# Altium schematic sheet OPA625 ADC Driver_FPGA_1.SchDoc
size 431 x 279 mm; Date: Not shown in title block; ApprovedBy: Not shown in title block; CheckedBy: Not shown in title block; Author: Not shown in title block; CompanyName: Not shown in title block; Engineer: Not shown in title block; Organization: Not shown in title block; Address1: Not shown in title block; Address2: Not shown in title block; Address3: Not shown in title block; Address4: Not shown in title block; DocumentNumber: 6; Revision: Use project parameter SCH_Rev; SheetNumber: 6; SheetTotal: 8; PageSetup: Record=PageOptions¦CenterHorizontal=True¦CenterVertical=True¦PrintScale=1.00¦XCorrection=1.00¦YCorrection=1.00¦PrintKind=0¦BorderSize=5000000¦LeftOffset=0¦BottomOffset=0¦Orientation=2¦PaperLength=1000¦PaperWidth=1000¦Scale=100¦PaperSource=15¦PrintQuality=600¦MediaType=1¦DitherType=10¦PaperKind=Letter¦PrintScaleMode=1
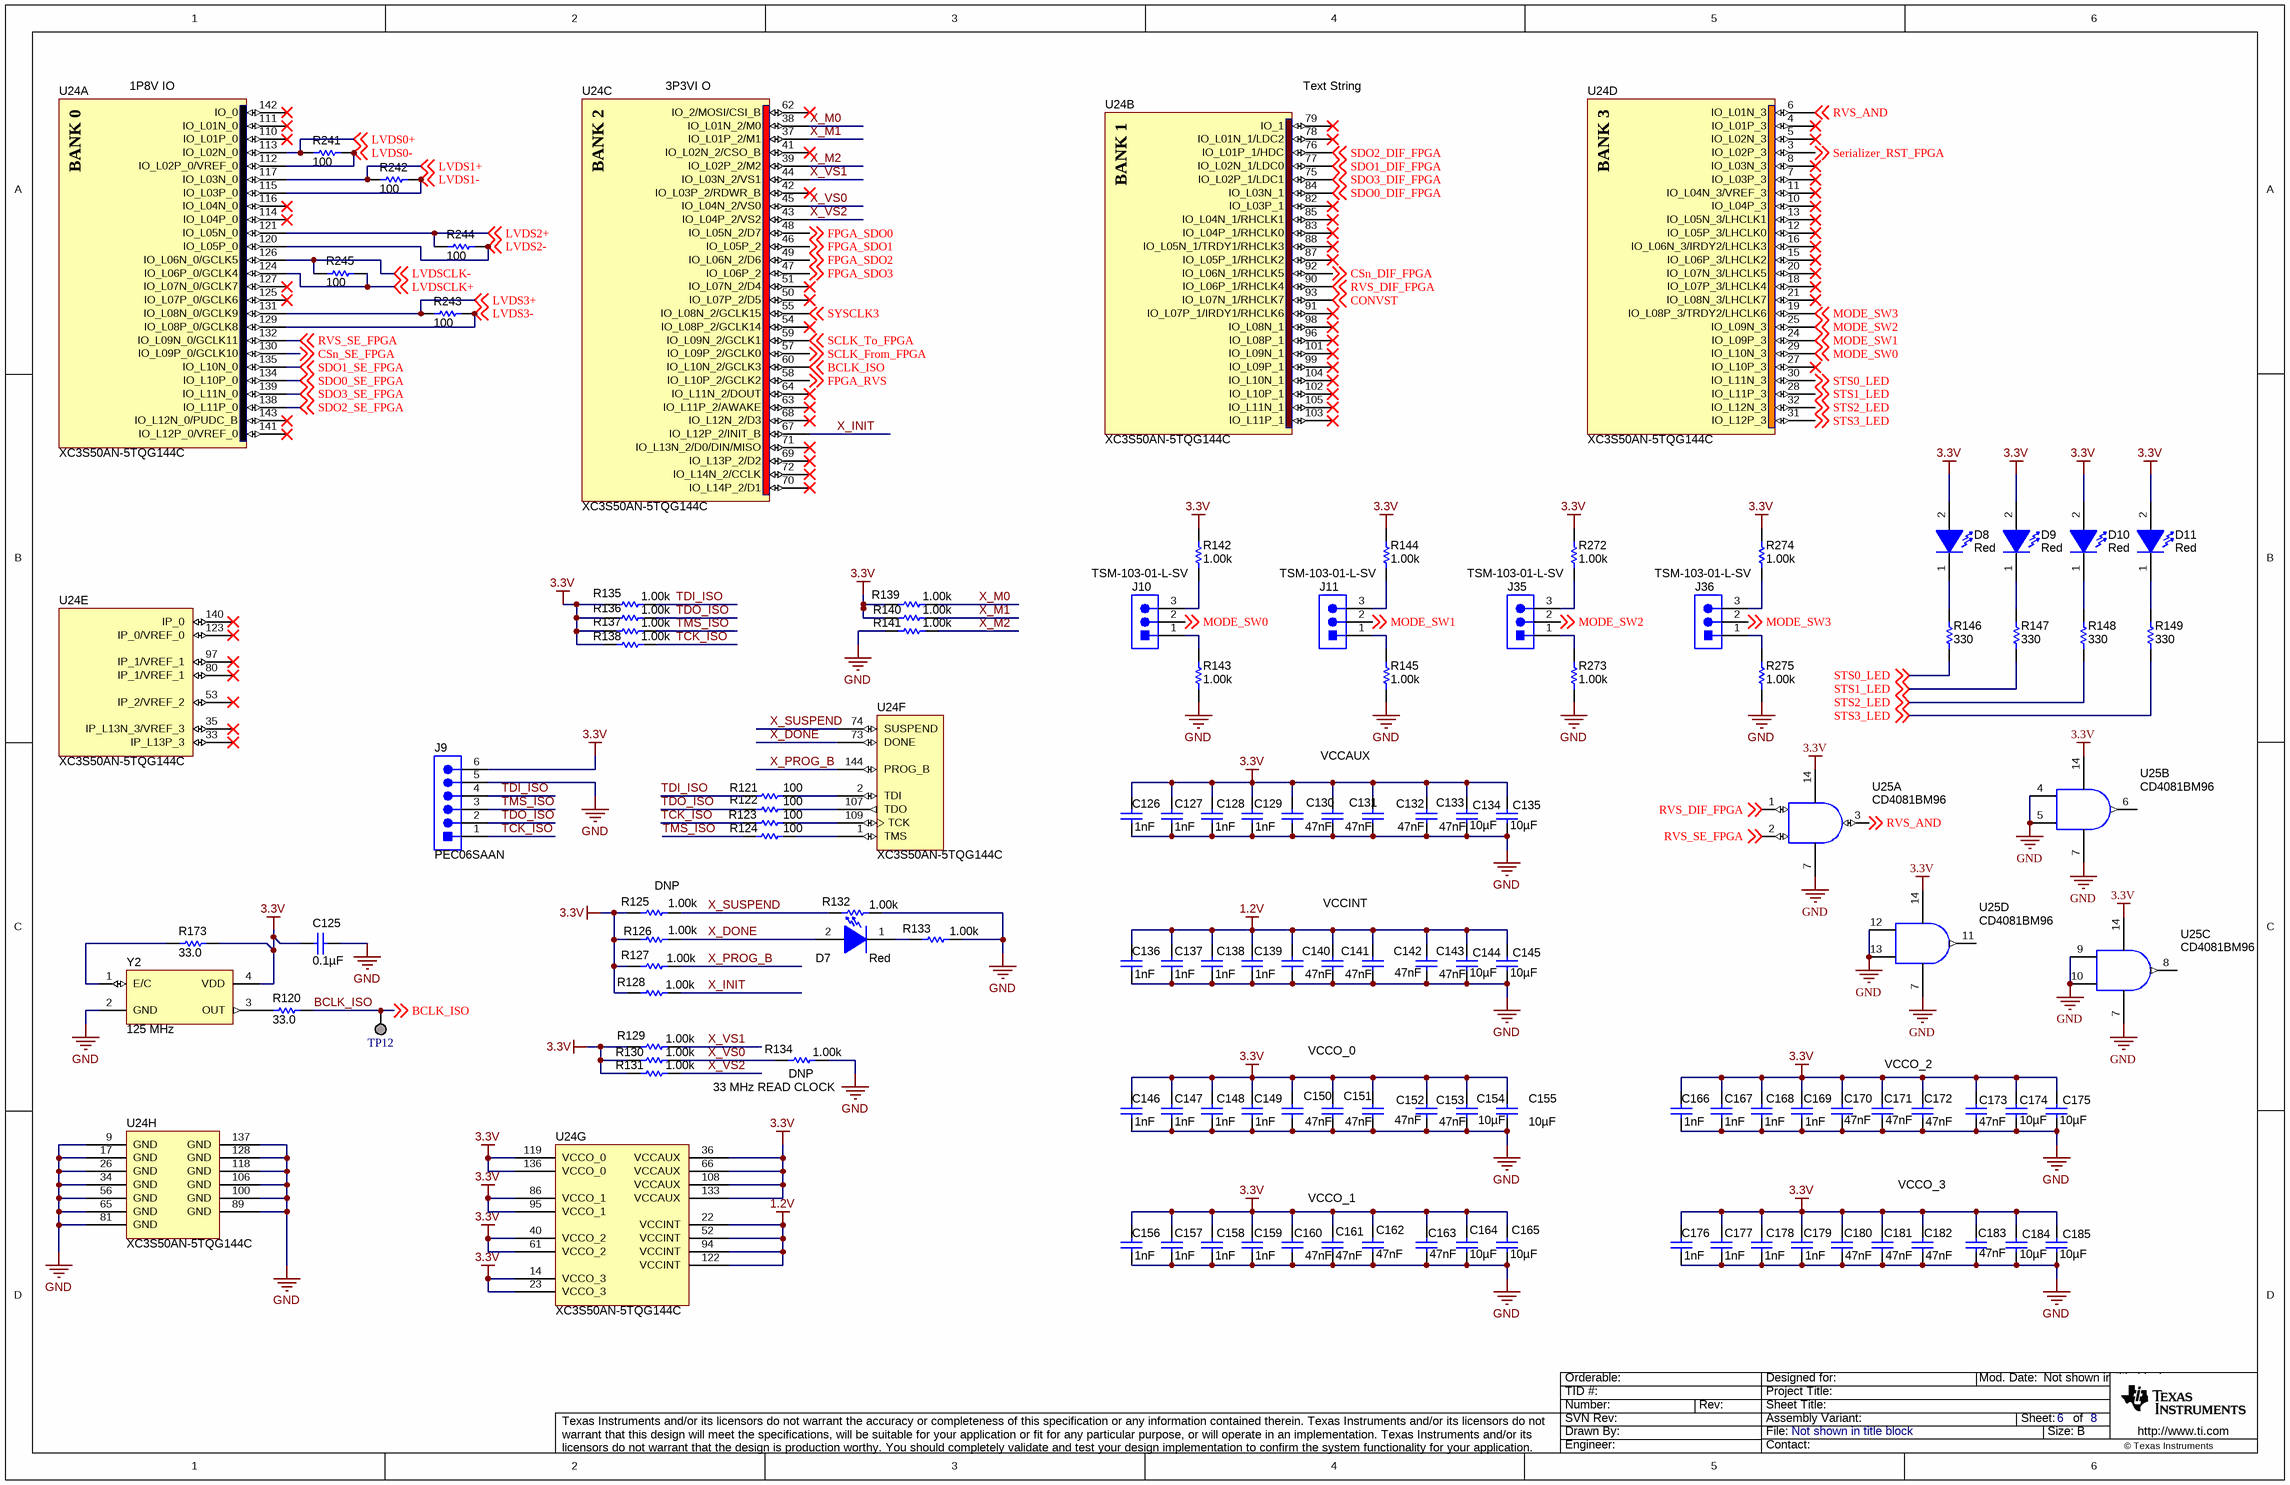
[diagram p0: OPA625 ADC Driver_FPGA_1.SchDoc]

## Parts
C125  ValueDisplayed: 0.1µF  [0402]  (hidden comment: GRM155R71C104KA88D)
C126  ValueDisplayed: 1nF  [0402]  (hidden comment: C1005X7R1H102M)
C127  ValueDisplayed: 1nF  [0402]  (hidden comment: C1005X7R1H102M)
C128  ValueDisplayed: 1nF  [0402]  (hidden comment: C1005X7R1H102M)
C129  ValueDisplayed: 1nF  [0402]  (hidden comment: C1005X7R1H102M)
C130  ValueDisplayed: 47nF  [0402]  (hidden comment: GRM155R61A473KA01D)
C131  ValueDisplayed: 47nF  [0402]  (hidden comment: GRM155R61A473KA01D)
C132  ValueDisplayed: 47nF  [0402]  (hidden comment: GRM155R61A473KA01D)
C133  ValueDisplayed: 47nF  [0402]  (hidden comment: GRM155R61A473KA01D)
C134  ValueDisplayed: 10µF  [0603_120]  (hidden comment: ZRB18AD71A106KE01L)
C135  ValueDisplayed: 10µF  [0603_120]  (hidden comment: ZRB18AD71A106KE01L)
C136  ValueDisplayed: 1nF  [0402]  (hidden comment: C1005X7R1H102M)
C137  ValueDisplayed: 1nF  [0402]  (hidden comment: C1005X7R1H102M)
C138  ValueDisplayed: 1nF  [0402]  (hidden comment: C1005X7R1H102M)
C139  ValueDisplayed: 1nF  [0402]  (hidden comment: C1005X7R1H102M)
C140  ValueDisplayed: 47nF  [0402]  (hidden comment: GRM155R61A473KA01D)
C141  ValueDisplayed: 47nF  [0402]  (hidden comment: GRM155R61A473KA01D)
C142  ValueDisplayed: 47nF  [0402]  (hidden comment: GRM155R61A473KA01D)
C143  ValueDisplayed: 47nF  [0402]  (hidden comment: GRM155R61A473KA01D)
C144  ValueDisplayed: 10µF  [0603_120]  (hidden comment: ZRB18AD71A106KE01L)
C145  ValueDisplayed: 10µF  [0603_120]  (hidden comment: ZRB18AD71A106KE01L)
C146  ValueDisplayed: 1nF  [0402]  (hidden comment: C1005X7R1H102M)
C147  ValueDisplayed: 1nF  [0402]  (hidden comment: C1005X7R1H102M)
C148  ValueDisplayed: 1nF  [0402]  (hidden comment: C1005X7R1H102M)
C149  ValueDisplayed: 1nF  [0402]  (hidden comment: C1005X7R1H102M)
C150  ValueDisplayed: 47nF  [0402]  (hidden comment: GRM155R61A473KA01D)
C151  ValueDisplayed: 47nF  [0402]  (hidden comment: GRM155R61A473KA01D)
C152  ValueDisplayed: 47nF  [0402]  (hidden comment: GRM155R61A473KA01D)
C153  ValueDisplayed: 47nF  [0402]  (hidden comment: GRM155R61A473KA01D)
C154  ValueDisplayed: 10µF  [0603_120]  (hidden comment: ZRB18AD71A106KE01L)
C155  ValueDisplayed: 10µF  [0603_120]  (hidden comment: ZRB18AD71A106KE01L)
C156  ValueDisplayed: 1nF  [0402]  (hidden comment: C1005X7R1H102M)
C157  ValueDisplayed: 1nF  [0402]  (hidden comment: C1005X7R1H102M)
C158  ValueDisplayed: 1nF  [0402]  (hidden comment: C1005X7R1H102M)
C159  ValueDisplayed: 1nF  [0402]  (hidden comment: C1005X7R1H102M)
C160  ValueDisplayed: 47nF  [0402]  (hidden comment: GRM155R61A473KA01D)
C161  ValueDisplayed: 47nF  [0402]  (hidden comment: GRM155R61A473KA01D)
C162  ValueDisplayed: 47nF  [0402]  (hidden comment: GRM155R61A473KA01D)
C163  ValueDisplayed: 47nF  [0402]  (hidden comment: GRM155R61A473KA01D)
C164  ValueDisplayed: 10µF  [0603_120]  (hidden comment: ZRB18AD71A106KE01L)
C165  ValueDisplayed: 10µF  [0603_120]  (hidden comment: ZRB18AD71A106KE01L)
C166  ValueDisplayed: 1nF  [0402]  (hidden comment: C1005X7R1H102M)
C167  ValueDisplayed: 1nF  [0402]  (hidden comment: C1005X7R1H102M)
C168  ValueDisplayed: 1nF  [0402]  (hidden comment: C1005X7R1H102M)
C169  ValueDisplayed: 1nF  [0402]  (hidden comment: C1005X7R1H102M)
C170  ValueDisplayed: 47nF  [0402]  (hidden comment: GRM155R61A473KA01D)
C171  ValueDisplayed: 47nF  [0402]  (hidden comment: GRM155R61A473KA01D)
C172  ValueDisplayed: 47nF  [0402]  (hidden comment: GRM155R61A473KA01D)
C173  ValueDisplayed: 47nF  [0402]  (hidden comment: GRM155R61A473KA01D)
C174  ValueDisplayed: 10µF  [0603_120]  (hidden comment: ZRB18AD71A106KE01L)
C175  ValueDisplayed: 10µF  [0603_120]  (hidden comment: ZRB18AD71A106KE01L)
C176  ValueDisplayed: 1nF  [0402]  (hidden comment: C1005X7R1H102M)
C177  ValueDisplayed: 1nF  [0402]  (hidden comment: C1005X7R1H102M)
C178  ValueDisplayed: 1nF  [0402]  (hidden comment: C1005X7R1H102M)
C179  ValueDisplayed: 1nF  [0402]  (hidden comment: C1005X7R1H102M)
C180  ValueDisplayed: 47nF  [0402]  (hidden comment: GRM155R61A473KA01D)
C181  ValueDisplayed: 47nF  [0402]  (hidden comment: GRM155R61A473KA01D)
C182  ValueDisplayed: 47nF  [0402]  (hidden comment: GRM155R61A473KA01D)
C183  ValueDisplayed: 47nF  [0402]  (hidden comment: GRM155R61A473KA01D)
C184  ValueDisplayed: 10µF  [0603_120]  (hidden comment: ZRB18AD71A106KE01L)
C185  ValueDisplayed: 10µF  [0603_120]  (hidden comment: ZRB18AD71A106KE01L)
D7  value Red  [WL-SMCW_RED]  (hidden comment: 150060RS75000)
D8  value Red  [WL-SMCW_RED]  (hidden comment: 150060RS75000)
D9  value Red  [WL-SMCW_RED]  (hidden comment: 150060RS75000)
D10  value Red  [WL-SMCW_RED]  (hidden comment: 150060RS75000)
D11  value Red  [WL-SMCW_RED]  (hidden comment: 150060RS75000)
J9  PEC06SAAN  [Sullins_PEC06SAAN]
J10  TSM-103-01-L-SV  [Samtec_TSM-103-01-X-SV]
J11  TSM-103-01-L-SV  [Samtec_TSM-103-01-X-SV]
J35  TSM-103-01-L-SV  [Samtec_TSM-103-01-X-SV]
J36  TSM-103-01-L-SV  [Samtec_TSM-103-01-X-SV]
R120  ValueDisplayed: 33.0  [0603]  (hidden comment: RC0603FR-0733RL)
R121  ValueDisplayed: 100  [0603]  (hidden comment: RG1608P-101-B-T5)
R122  ValueDisplayed: 100  [0603]  (hidden comment: RG1608P-101-B-T5)
R123  ValueDisplayed: 100  [0603]  (hidden comment: RG1608P-101-B-T5)
R124  ValueDisplayed: 100  [0603]  (hidden comment: RG1608P-101-B-T5)
R125  ValueDisplayed: 1.00k  [0603]  (hidden comment: RC0603FR-071KL)
R126  ValueDisplayed: 1.00k  [0603]  (hidden comment: RC0603FR-071KL)
R127  ValueDisplayed: 1.00k  [0603]  (hidden comment: RC0603FR-071KL)
R128  ValueDisplayed: 1.00k  [0603]  (hidden comment: RC0603FR-071KL)
R129  ValueDisplayed: 1.00k  [0603]  (hidden comment: RC0603FR-071KL)
R130  ValueDisplayed: 1.00k  [0603]  (hidden comment: RC0603FR-071KL)
R131  ValueDisplayed: 1.00k  [0603]  (hidden comment: RC0603FR-071KL)
R132  ValueDisplayed: 1.00k  [0603]  (hidden comment: RC0603FR-071KL)
R133  ValueDisplayed: 1.00k  [0603]  (hidden comment: RC0603FR-071KL)
R134  ValueDisplayed: 1.00k  [0603]  (hidden comment: RC0603FR-071KL)
R135  ValueDisplayed: 1.00k  [0603]  (hidden comment: RC0603FR-071KL)
R136  ValueDisplayed: 1.00k  [0603]  (hidden comment: RC0603FR-071KL)
R137  ValueDisplayed: 1.00k  [0603]  (hidden comment: RC0603FR-071KL)
R138  ValueDisplayed: 1.00k  [0603]  (hidden comment: RC0603FR-071KL)
R139  ValueDisplayed: 1.00k  [0603]  (hidden comment: RC0603FR-071KL)
R140  ValueDisplayed: 1.00k  [0603]  (hidden comment: RC0603FR-071KL)
R141  ValueDisplayed: 1.00k  [0603]  (hidden comment: RC0603FR-071KL)
R142  ValueDisplayed: 1.00k  [0603]  (hidden comment: RC0603FR-071KL)
R143  ValueDisplayed: 1.00k  [0603]  (hidden comment: RC0603FR-071KL)
R144  ValueDisplayed: 1.00k  [0603]  (hidden comment: RC0603FR-071KL)
R145  ValueDisplayed: 1.00k  [0603]  (hidden comment: RC0603FR-071KL)
R146  ValueDisplayed: 330  [0603]  (hidden comment: RC0603JR-07330RL)
R147  ValueDisplayed: 330  [0603]  (hidden comment: RC0603JR-07330RL)
R148  ValueDisplayed: 330  [0603]  (hidden comment: RC0603JR-07330RL)
R149  ValueDisplayed: 330  [0603]  (hidden comment: RC0603JR-07330RL)
R173  ValueDisplayed: 33.0  [0603]  (hidden comment: RC0603FR-0733RL)
R241  ValueDisplayed: 100  [0402L]  (hidden comment: MCS0402MD1000BE100)
R242  ValueDisplayed: 100  [0402L]  (hidden comment: MCS0402MD1000BE100)
R243  ValueDisplayed: 100  [0402L]  (hidden comment: MCS0402MD1000BE100)
R244  ValueDisplayed: 100  [0402L]  (hidden comment: MCS0402MD1000BE100)
R245  ValueDisplayed: 100  [0402L]  (hidden comment: MCS0402MD1000BE100)
R272  ValueDisplayed: 1.00k  [0603]  (hidden comment: RC0603FR-071KL)
R273  ValueDisplayed: 1.00k  [0603]  (hidden comment: RC0603FR-071KL)
R274  ValueDisplayed: 1.00k  [0603]  (hidden comment: RC0603FR-071KL)
R275  ValueDisplayed: 1.00k  [0603]  (hidden comment: RC0603FR-071KL)
TP12  Pogo Pad  [PogoPad]  (value not drawn)  (no BOM)
U24  XC3S50AN-5TQG144C  [TQ144_N]  (parts A,B,C,D,E,F,G,H of 8)
U25  CD4081BM96  [D0014A_N]  (parts A,B,C,D of 4)
Y2  Frequency: 125 MHz  [Vectron_VCC1]  (hidden comment: VCC1-B3B-125M000000)

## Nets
1.2V: C136.1 C137.1 C138.1 C139.1 C140.1 C141.1 C142.1 C143.1 C144.1 C145.1 U24.22(VCCINT) U24.52(VCCINT) U24.94(VCCINT) U24.122(VCCINT)
3.3V: C125.1 C126.1 C127.1 C128.1 C129.1 C130.1 C131.1 C132.1 C133.1 C134.1 C135.1 C146.1 C147.1 C148.1 C149.1 C150.1 C151.1 C152.1 C153.1 C154.1 C155.1 C156.1 C157.1 C158.1 C159.1 C160.1 C161.1 C162.1 C163.1 C164.1 C165.1 C166.1 C167.1 C168.1 C169.1 C170.1 C171.1 C172.1 C173.1 C174.1 C175.1 C176.1 C177.1 C178.1 C179.1 C180.1 C181.1 C182.1 C183.1 C184.1 C185.1 D8.2(A) D9.2(A) D10.2(A) D11.2(A) J9.6 R125.2 R126.1 R127.1 R128.1 R129.1 R130.1 R131.1 R135.1 R136.1 R137.1 R138.1 R139.1 R140.1 R142.2 R144.2 R173.2 R272.2 R274.2 U24.14(VCCO_3) U24.23(VCCO_3) U24.36(VCCAUX) U24.40(VCCO_2) U24.61(VCCO_2) U24.66(VCCAUX) U24.86(VCCO_1) U24.95(VCCO_1) U24.108(VCCAUX) U24.119(VCCO_0) U24.133(VCCAUX) U24.136(VCCO_0) U25.14(VCC) Y2.4(VDD)
GND: C125.2 C126.2 C127.2 C128.2 C129.2 C130.2 C131.2 C132.2 C133.2 C134.2 C135.2 C136.2 C137.2 C138.2 C139.2 C140.2 C141.2 C142.2 C143.2 C144.2 C145.2 C146.2 C147.2 C148.2 C149.2 C150.2 C151.2 C152.2 C153.2 C154.2 C155.2 C156.2 C157.2 C158.2 C159.2 C160.2 C161.2 C162.2 C163.2 C164.2 C165.2 C166.2 C167.2 C168.2 C169.2 C170.2 C171.2 C172.2 C173.2 C174.2 C175.2 C176.2 C177.2 C178.2 C179.2 C180.2 C181.2 C182.2 C183.2 C184.2 C185.2 J9.5 R132.1 R133.1 R134.2 R141.1 R143.1 R145.1 R273.1 R275.1 U24.9(GND) U24.17(GND) U24.26(GND) U24.34(GND) U24.56(GND) U24.65(GND) U24.81(GND) U24.89(GND) U24.100(GND) U24.106(GND) U24.118(GND) U24.128(GND) U24.137(GND) U25.4(2A) U25.5(2B) U25.7(GND) U25.9(3A) U25.10(3B) U25.12(4A) U25.13(4B) Y2.2(GND)
BCLK_ISO: R120.2 TP12.1 U24.60(IO_L10N_2/GCLK3) ; off-sheet BCLK_ISO
CONVST: U24.93(IO_L07N_1/RHCLK7) ; off-sheet CONVST
CSn_DIF_FPGA: U24.92(IO_L06N_1/RHCLK5) ; off-sheet CSn_DIF_FPGA
CSn_SE_FPGA: U24.130(IO_L09P_0/GCLK10) ; off-sheet CSn_SE_FPGA
FPGA_RVS: U24.58(IO_L10P_2/GCLK2) ; off-sheet FPGA_RVS
FPGA_SDO0: U24.48(IO_L05N_2/D7) ; off-sheet FPGA_SDO0
FPGA_SDO1: U24.46(IO_L05P_2) ; off-sheet FPGA_SDO1
FPGA_SDO2: U24.49(IO_L06N_2/D6) ; off-sheet FPGA_SDO2
FPGA_SDO3: U24.47(IO_L06P_2) ; off-sheet FPGA_SDO3
LVDS0+: R241.1 U24.113(IO_L02N_0) ; off-sheet LVDS0+
LVDS0-: R241.2 U24.112(IO_L02P_0/VREF_0) ; off-sheet LVDS0-
LVDS1+: R242.1 U24.117(IO_L03N_0) ; off-sheet LVDS1+
LVDS1-: R242.2 U24.115(IO_L03P_0) ; off-sheet LVDS1-
LVDS2+: R244.1 U24.121(IO_L05N_0) ; off-sheet LVDS2+
LVDS2-: R244.2 U24.120(IO_L05P_0) ; off-sheet LVDS2-
LVDS3+: R243.1 U24.131(IO_L08N_0/GCLK9) ; off-sheet LVDS3+
LVDS3-: R243.2 U24.129(IO_L08P_0/GCLK8) ; off-sheet LVDS3-
LVDSCLK+: R245.2 U24.124(IO_L06P_0/GCLK4) ; off-sheet LVDSCLK+
LVDSCLK-: R245.1 U24.126(IO_L06N_0/GCLK5) ; off-sheet LVDSCLK-
MODE_SW0: J10.2 U24.29(IO_L10N_3) ; off-sheet MODE_SW0
MODE_SW1: J11.2 U24.24(IO_L09P_3) ; off-sheet MODE_SW1
MODE_SW2: J35.2 U24.25(IO_L09N_3) ; off-sheet MODE_SW2
MODE_SW3: J36.2 U24.19(IO_L08P_3/TRDY2/LHCLK6) ; off-sheet MODE_SW3
RVS_AND: U24.6(IO_L01N_3) U25.3(1Y) ; off-sheet RVS_AND
RVS_DIF_FPGA: U24.90(IO_L06P_1/RHCLK4) U25.1(1A) ; off-sheet RVS_DIF_FPGA
RVS_SE_FPGA: U24.132(IO_L09N_0/GCLK11) U25.2(1B) ; off-sheet RVS_SE_FPGA
SCLK_From_FPGA: U24.57(IO_L09P_2/GCLK0) ; off-sheet SCLK_From_FPGA
SCLK_To_FPGA: U24.59(IO_L09N_2/GCLK1) ; off-sheet SCLK_To_FPGA
SDO0_DIF_FPGA: U24.84(IO_L03N_1) ; off-sheet SDO0_DIF_FPGA
SDO0_SE_FPGA: U24.134(IO_L10P_0) ; off-sheet SDO0_SE_FPGA
SDO1_DIF_FPGA: U24.77(IO_L02N_1/LDC0) ; off-sheet SDO1_DIF_FPGA
SDO1_SE_FPGA: U24.135(IO_L10N_0) ; off-sheet SDO1_SE_FPGA
SDO2_DIF_FPGA: U24.76(IO_L01P_1/HDC) ; off-sheet SDO2_DIF_FPGA
SDO2_SE_FPGA: U24.138(IO_L11P_0) ; off-sheet SDO2_SE_FPGA
SDO3_DIF_FPGA: U24.75(IO_L02P_1/LDC1) ; off-sheet SDO3_DIF_FPGA
SDO3_SE_FPGA: U24.139(IO_L11N_0) ; off-sheet SDO3_SE_FPGA
Serializer_RST_FPGA: U24.3(IO_L02P_3) ; off-sheet Serializer_RST_FPGA
STS0_LED: R146.1 U24.30(IO_L11N_3) ; off-sheet STS0_LED
STS1_LED: R147.1 U24.28(IO_L11P_3) ; off-sheet STS1_LED
STS2_LED: R148.1 U24.32(IO_L12N_3) ; off-sheet STS2_LED
STS3_LED: R149.1 U24.31(IO_L12P_3) ; off-sheet STS3_LED
SYSCLK3: U24.55(IO_L08N_2/GCLK15) ; off-sheet SYSCLK3
TCK_ISO: J9.1 R123.1 R138.2
TDI_ISO: J9.4 R121.1 R135.2
TDO_ISO: J9.2 R122.1 R136.2
TMS_ISO: J9.3 R124.1 R137.2
X_DONE: D7.2(A) R126.2 U24.73(DONE)
X_INIT: R128.2 U24.67(IO_L12P_2/INIT_B)
X_M0: R139.2 U24.38(IO_L01N_2/M0)
X_M1: R140.2 U24.37(IO_L01P_2/M1)
X_M2: R141.2 U24.39(IO_L02P_2/M2)
X_PROG_B: R127.2 U24.144(PROG_B)
X_SUSPEND: R125.1 R132.2 U24.74(SUSPEND)
X_VS0: R130.2 R134.1 U24.45(IO_L04N_2/VS0)
X_VS1: R129.2 U24.44(IO_L03N_2/VS1)
X_VS2: R131.2 U24.43(IO_L04P_2/VS2)
NetD7_1: D7.1(K) R133.2
NetD8_1: D8.1(K) R146.2
NetD9_1: D9.1(K) R147.2
NetD10_1: D10.1(K) R148.2
NetD11_1: D11.1(K) R149.2
NetJ10_1: J10.1 R143.2
NetJ10_3: J10.3 R142.1
NetJ11_1: J11.1 R145.2
NetJ11_3: J11.3 R144.1
NetJ35_1: J35.1 R273.2
NetJ35_3: J35.3 R272.1
NetJ36_1: J36.1 R275.2
NetJ36_3: J36.3 R274.1
NetR120_1: R120.1 Y2.3(OUT)
NetR121_2: R121.2 U24.2(TDI)
NetR122_2: R122.2 U24.107(TDO)
NetR123_2: R123.2 U24.109(TCK)
NetR124_2: R124.2 U24.1(TMS)
NetR173_1: R173.1 Y2.1(E/C)

Not connected (* = marked no-connect by the designer): U24 4(IO_L01P_3)* 5(IO_L02N_3)* 7(IO_L03P_3)* 8(IO_L03N_3)* 10(IO_L04P_3)* 11(IO_L04N_3/VREF_3)* 12(IO_L05P_3/LHCLK0)* 13(IO_L05N_3/LHCLK1)* 15(IO_L06P_3/LHCLK2)* 16(IO_L06N_3/IRDY2/LHCLK3)* 18(IO_L07P_3/LHCLK4)* 20(IO_L07N_3/LHCLK5)* 21(IO_L08N_3/LHCLK7)* 27(IO_L10P_3)* 33(IP_L13P_3)* 35(IP_L13N_3/VREF_3)* 41(IO_L02N_2/CSO_B)* 42(IO_L03P_2/RDWR_B)* 50(IO_L07P_2/D5)* 51(IO_L07N_2/D4)* 53(IP_2/VREF_2)* 54(IO_L08P_2/GCLK14)* 62(IO_2/MOSI/CSI_B)* 63(IO_L11P_2/AWAKE)* 64(IO_L11N_2/DOUT)* 68(IO_L12N_2/D3)* 69(IO_L13P_2/D2)* 70(IO_L14P_2/D1)* 71(IO_L13N_2/D0/DIN/MISO)* 72(IO_L14N_2/CCLK)* 78(IO_L01N_1/LDC2)* 79(IO_1)* 80(IP_1/VREF_1)* 82(IO_L03P_1)* 83(IO_L04P_1/RHCLK0)* 85(IO_L04N_1/RHCLK1)* 87(IO_L05P_1/RHCLK2)* 88(IO_L05N_1/TRDY1/RHCLK3)* 91(IO_L07P_1/IRDY1/RHCLK6)* 96(IO_L08P_1)* 97(IP_1/VREF_1)* 98(IO_L08N_1)* 99(IO_L09P_1)* 101(IO_L09N_1)* 102(IO_L10P_1)* 103(IO_L11P_1)* 104(IO_L10N_1)* 105(IO_L11N_1)* 110(IO_L01P_0)* 111(IO_L01N_0)* 114(IO_L04P_0)* 116(IO_L04N_0)* 123(IP_0/VREF_0)* 125(IO_L07P_0/GCLK6)* 127(IO_L07N_0/GCLK7)* 140(IP_0)* 141(IO_L12P_0/VREF_0)* 142(IO_0)* 143(IO_L12N_0/PUDC_B)*; U25 6(2Y) 8(3Y) 11(4Y)

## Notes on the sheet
- 1P8V IO
- 3P3VI O
- (near U24) Text String
- VCCAUX
- (near R125) DNP
- VCCINT
- (near R134) 33 MHz READ CLOCK
- (near R134) DNP
- VCCO_0
- VCCO_2
- VCCO_1
- VCCO_3

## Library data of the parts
C125 = GRM155R71C104KA88D: CAP, CERM, 0.1 µF, 16 V, +/- 10%, X7R, 0402; Manufacturer: MuRata; Polarized: N; CompType: Capacitor; Value: 0.1uF; U/M: EA; Cap_F: 0.0000001; Tolerance_%: 10; Value1: Unknown; VDC_V: 16; Value2: 16V; TaMin_C: -55; TaMax_C: 125
C126-C129 C136-C139 C146-C149 C156-C159 C166-C169 C176-C179 = C1005X7R1H102M: CAP, CERM, 1000 pF, 50 V, +/- 20%, X7R, 0402; Manufacturer: TDK; Polarized: N; CompType: Capacitor; Value: 1000pF; U/M: EA; Cap_F: 0.000000001; Tolerance_%: 20; ESR_ohm: 0.005; Value1: 0.005 ohm; VDC_V: 50; Value2: 50V; TaMin_C: -55; TaMax_C: 125; AEC Category: Q200
C130-C133 C140-C143 C150-C153 C160-C163 C170-C173 C180-C183 = GRM155R61A473KA01D: CAP, CERM, 0.047 µF, 10 V, +/- 10%, X5R, 0402; Manufacturer: MuRata; Polarized: N; CompType: Capacitor; Value: 0.047uF; U/M: EA; Cap_F: 0.000000047; Tolerance_%: 10; Value1: Unknown; Value2: 10V; TaMin_C: -55; TaMax_C: 85; AEC Category: Q200
C134 C135 C144 C145 C154 C155 C164 C165 C174 C175 C184 C185 = ZRB18AD71A106KE01L: CAP, CERM, 10 µF, 10 V, +/- 10%, X7T, 0603; Manufacturer: MuRata; Polarized: N; CompType: Capacitor; Value: 10uF; U/M: EA; Cap_F: 0.00001; Tolerance_%: 10; Value1: Unknown; Value2: 10V; TaMin_C: -55; TaMax_C: 125; Cap_Case: 0603; AEC Category: Q200
D7-D11 = 150060RS75000: LED, Red, SMD; Manufacturer: Wurth Elektronik; Type: AlInGaP; Vf_V: 2; Value2: 2V; Io_A: 0.03; Vr_V: 5; Tjmax_C: 85; Power_TotalModule: 0.072; Value1: 0.072W; Angle: 140; U/M: EA
J9 = PEC06SAAN: Header, 100mil, 6x1, Tin, TH; Manufacturer: Sullins Connector Solutions; SymbolCreator: a0412235; U/M: EA
J10 J11 J35 J36 = TSM-103-01-L-SV: Header, 100mil, 3x1, Gold, SMT; Manufacturer: Samtec; SymbolCreator: a0799628; U/M: EA
R120 R173 = RC0603FR-0733RL: RES, 33.0, 1%, 0.1 W, 0603; Manufacturer: Yageo America; CompType: Resistor; Value: 33.0; Res_ohm: 33; Value_Code: 33R0; Tolerance_%: 1; Power_W: 0.1; Value2: 0.1W; VDC_V: 150; TempCo: 200 ppm/C; U/M: EA; AEC Category: Q200
R121-R124 = RG1608P-101-B-T5: RES, 100, 0.1%, 0.1 W, 0603; Manufacturer: Susumu Co Ltd; CompType: Resistor; Value: 100; Value_Code: 100R; Tolerance_%: 0.1; Value2: 0.1W; VDC_V: 75; TempCo: 25 ppm/C; EIA_Code: E192; U/M: EA; AEC Category: Q200
R125-R145 R272-R275 = RC0603FR-071KL: RES, 1.00 k, 1%, 0.1 W, 0603; Manufacturer: Yageo America; CompType: Resistor; Value: 1.00k; Res_ohm: 1000; Value_Code: 1k00; Tolerance_%: 1; Power_W: 0.1; Value2: 0.1W; VDC_V: 150; TempCo: 200 ppm/C; EIA_Code: E96; U/M: EA; AEC Category: Q200
R146-R149 = RC0603JR-07330RL: RES, 330, 5%, 0.1 W, 0603; Manufacturer: Yageo America; CompType: Resistor; Value: 330; Value_Code: 330R; Tolerance_%: 5; Power_W: 0.1; Value2: 0.1W; VDC_V: 50; TempCo: 100 ppm/C; EIA_Code: E24; U/M: EA; AEC Category: Q200
R241-R245 = MCS0402MD1000BE100: RES, 100, 0.1%, 0.1 W, AEC-Q200 Grade 0, 0402; Manufacturer: Vishay/Beyschlag; CompType: Resistor; Value: 100; Value_Code: 100R; Tolerance_%: 0.1; Value2: 0.1W; VDC_V: 50; TempCo: 25 ppm/C; SizeArea_mm2: 0.5; SizeX_mm: 1; SizeZ_mm: 0.6; EIA_Code: E192; U/M: EA; AEC Category: Q200; AEC Qualified: Y; AEC Grade: 0
TP12 = PogoPad: Pad for Pogo Pin Connector; SymbolCreator: codlsc
U24 = XC3S50AN-4TQ144C: Spartan-3AN Non-Volatile FPGA, 108 User I/Os, 144-Pin TQFP, Standard Performance, Commercial Grade
U25 = CD4081BM96: Quad 2-Input AND Gate, D0014A; Manufacturer: Texas Instruments; SymbolCreator: a0411947; SizeArea_mm2: 51.9; SizeAreaWB_mm2: 85.2; SizeX_mm: 6; SizeY_mm: 8.65; SizeZ_mm: 1.75; CompType: IC; U/M: EA
Y2 = VCC1-B3B-125M000000: OSC, 3.3 V, 125 MHz, 15 pF, SMD; Manufacturer: Vectron; SymbolCreator: a0799628; CompType: Oscillator; U/M: EA; TaMin_C: -10; TaMax_C: 70; Frequency Stability: ±50ppm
